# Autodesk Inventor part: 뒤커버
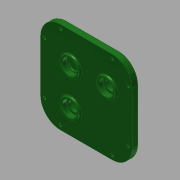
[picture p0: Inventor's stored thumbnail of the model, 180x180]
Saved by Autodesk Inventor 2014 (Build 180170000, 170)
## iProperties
Created: 2016-12
Part Number: 뒤커버
Material: 일반
Document SubType Name: Modeling
Designer: mduedu
Density: 1 g/cm^3
Appearance: 매끄러움 - 짙은 산림 녹색
Mass: 179.104 g
Surface Area: 454.562 cm^2
Volume: 179.104 cm^3
Author: mduedu
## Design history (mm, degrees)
sketch "스케치1"
  geometry: L1 (-46, 42)-(-46, -36); L2 (-16, 72)-(62, 72); L3 (92, 42)-(92, -36); L4 (62, -66)-(-16, -66); A1 r 30 centre (-16, -36) between (-46, -36) and (-16, -66); A2 r 30 centre (62, 42) between (92, 42) and (62, 72); A3 r 30 centre (62, -36) between (62, -66) and (92, -36); A4 r 30 centre (-16, 42) between (-16, 72) and (-46, 42); 1 further point
  constraints: 8 end point, 8 point on circle, 8 tangent, 4 centre point, 3 equal radius, 2 perpendicular, 1 horizontal, 1 vertical
  dimensions: "d80" = 30 radius of A2; "d81" = 138 distance between parallel lines of L4 L2; "d82" = 92 distance from line of L3 point (0, 0); "d114" = 46 distance from line of L1 point (0, 0); "d115" = 72 distance from line of L2 point (0, 0)
extrude "돌출1" new body sketch "스케치1" distance "d3" = 10; taper "d4" = 0 deg
sketch "스케치2"
  geometry: C1 r 14 at (0, 26); 1 further point
  constraints: 1 centre point, 1 vertical alignment
  dimensions: "d5" = 28 diameter of C1; "d6" = 26 distance of C1.centre point (0, 0)
extrude "돌출2" join sketch "스케치2" distance "d7" = 3; taper "d8" = 0 deg
sketch "스케치3"
  geometry: C1 r 14 at (0, -28.87); C2 r 14 at (0, 26) reference; C3 r 14 at (54.87, 26); 1 further point
  constraints: 2 centre point, 1 horizontal alignment, 1 vertical alignment
  dimensions: "d9" = 28 diameter of C1; "d69" = 54.87 distance of C1.centre C2.centre; "d83" = 28 diameter of C3; "d84" = 54.87 distance of C3.centre C2.centre
extrude "돌출3" join sketch "스케치3" distance "d11" = 3; taper "d12" = 0 deg
hole "구멍1" diameter "d15" = 22; stored, may be unused: countersink angle "d19" = 90 deg, drill point angle "d21" = 0 deg; dims "d13" = 10, "d14" = 10, "d16" = 6, "d17" = 4, "d18" = 2, "d20" = 7
hole "구멍2" diameter "d24" = 18; stored, may be unused: countersink angle "d28" = 90 deg, drill point angle "d30" = 0 deg; dims "d22" = 10, "d23" = 10, "d25" = 6, "d26" = 4, "d27" = 2, "d29" = 1
hole "구멍3" diameter "d33" = 22; stored, may be unused: countersink angle "d37" = 90 deg, drill point angle "d39" = 0 deg; dims "d31" = 10, "d32" = 10, "d34" = 6, "d35" = 4, "d36" = 2, "d38" = 7
hole "구멍7" diameter "d87" = 22; stored, may be unused: countersink angle "d91" = 90 deg, drill point angle "d93" = 0 deg; dims "d85" = 10, "d86" = 10, "d88" = 6, "d89" = 4, "d90" = 2, "d92" = 7
sketch "스케치4"
  geometry: C1 r 14 at (0, -28.87) reference; C2 r 18 at (0, -28.87); C3 r 14 at (-54.87, 26) reference; C4 r 18 at (-54.87, 26); 1 further point
  constraints: 2 centre point, 2 coincident
  dimensions: "d40" = 36 diameter of C2; "d94" = 36 diameter of C4
extrude "돌출4" join sketch "스케치4" distance "d41" = 4; taper "d42" = 0 deg
hole "구멍4" diameter "d45" = 22; stored, may be unused: countersink angle "d49" = 90 deg, drill point angle "d51" = 0 deg; dims "d43" = 10, "d44" = 10, "d46" = 6, "d47" = 4, "d48" = 2, "d50" = 7
hole "구멍8" diameter "d97" = 22; stored, may be unused: countersink angle "d101" = 90 deg, drill point angle "d103" = 0 deg; dims "d95" = 10, "d96" = 10, "d98" = 6, "d99" = 4, "d100" = 2, "d102" = 7
hole "구멍5" diameter "d54" = 15; stored, may be unused: countersink angle "d58" = 90 deg, drill point angle "d60" = 0 deg; dims "d52" = 10, "d53" = 10, "d55" = 6, "d56" = 4, "d57" = 2, "d59" = 7
hole "구멍9" diameter "d106" = 15; stored, may be unused: countersink angle "d110" = 90 deg, drill point angle "d112" = 0 deg; dims "d104" = 10, "d105" = 10, "d107" = 6, "d108" = 4, "d109" = 2, "d111" = 7
fillet "모깎기1" dims "d61" = 0.3
fillet "모깎기2" dims "d62" = 2
chamfer "모따기1" distance "d63" = 1; stored, may be unused: second distance "d64" = 2, angle "d65" = 45 deg
fillet "모깎기3" dims "d66" = 2
fillet "모깎기4" dims "d67" = 2
fillet "모깎기5" dims "d68" = 2
sketch "스케치5"
  geometry: L1 (-62, 72)-(16, 72) reference; L2 (-92, -36)-(-92, 42) reference; L3 (16, -66)-(-62, -66) reference; L4 (46, 42)-(46, -36) reference; L5 (16, 66)-(-62, 66); L6 (-86, 42)-(-86, -36); L7 (-62, -60)-(16, -60); L8 (40, -36)-(40, 42); A1 r 30 centre (-62, 42) between (-62, 72) and (-92, 42) reference; A2 r 30 centre (-62, -36) between (-92, -36) and (-62, -66) reference; A3 r 30 centre (16, -36) between (16, -66) and (46, -36) reference; A4 r 30 centre (16, 42) between (46, 42) and (16, 72) reference; A5 r 24 centre (-62, 42) between (-62, 66) and (-86, 42); A6 r 24 centre (-62, -36) between (-86, -36) and (-62, -60); A7 r 24 centre (16, -36) between (16, -60) and (40, -36); A8 r 24 centre (16, 42) between (40, 42) and (16, 66)
  constraints: 8 end point, 8 point on circle, 4 centre point, 7 other
  dimensions: "d113" = 6 distance between parallel lines of L6 L2
sketch "스케치6"
  geometry: L1 (16, 66)-(-62, 66) reference; L2 (40, -36)-(40, 42) reference; L3 (-62, -60)-(16, -60) reference; L4 (-86, 42)-(-86, -36) reference; A1 r 24 centre (16, 42) between (40, 42) and (16, 66) reference; A2 r 24 centre (16, -36) between (16, -60) and (40, -36) reference; A3 r 24 centre (-62, -36) between (-86, -36) and (-62, -60) reference; A4 r 24 centre (-62, 42) between (-62, 66) and (-86, 42) reference; 8 further points
  constraints: 8 coincident
hole "구멍6" sketch "스케치6" at (-62, 66), (-86, 42), (-86, -36), (-62, -60), (16, -60), (40, -36), (40, 42), (16, 66) diameter "d71" = 4.5; stored, may be unused: countersink angle "d75" = 90 deg, drill point angle "d77" = 0 deg; dims "d72" = 6, "d73" = 8, "d74" = 4.6, "d76" = 8
node "솔리드1"
